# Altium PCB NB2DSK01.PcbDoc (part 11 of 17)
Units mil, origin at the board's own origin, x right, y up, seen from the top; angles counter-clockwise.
Board outline 11815 x 6500.03 mil, 8 copper layers (Top Layer, MidLayer1, MidLayer2, GND, PWR, MidLayer3, MidLayer4, Bottom Layer), stack 74.62 mil thick; 798 components, 1002 nets, 3927 pads, 3182 vias.
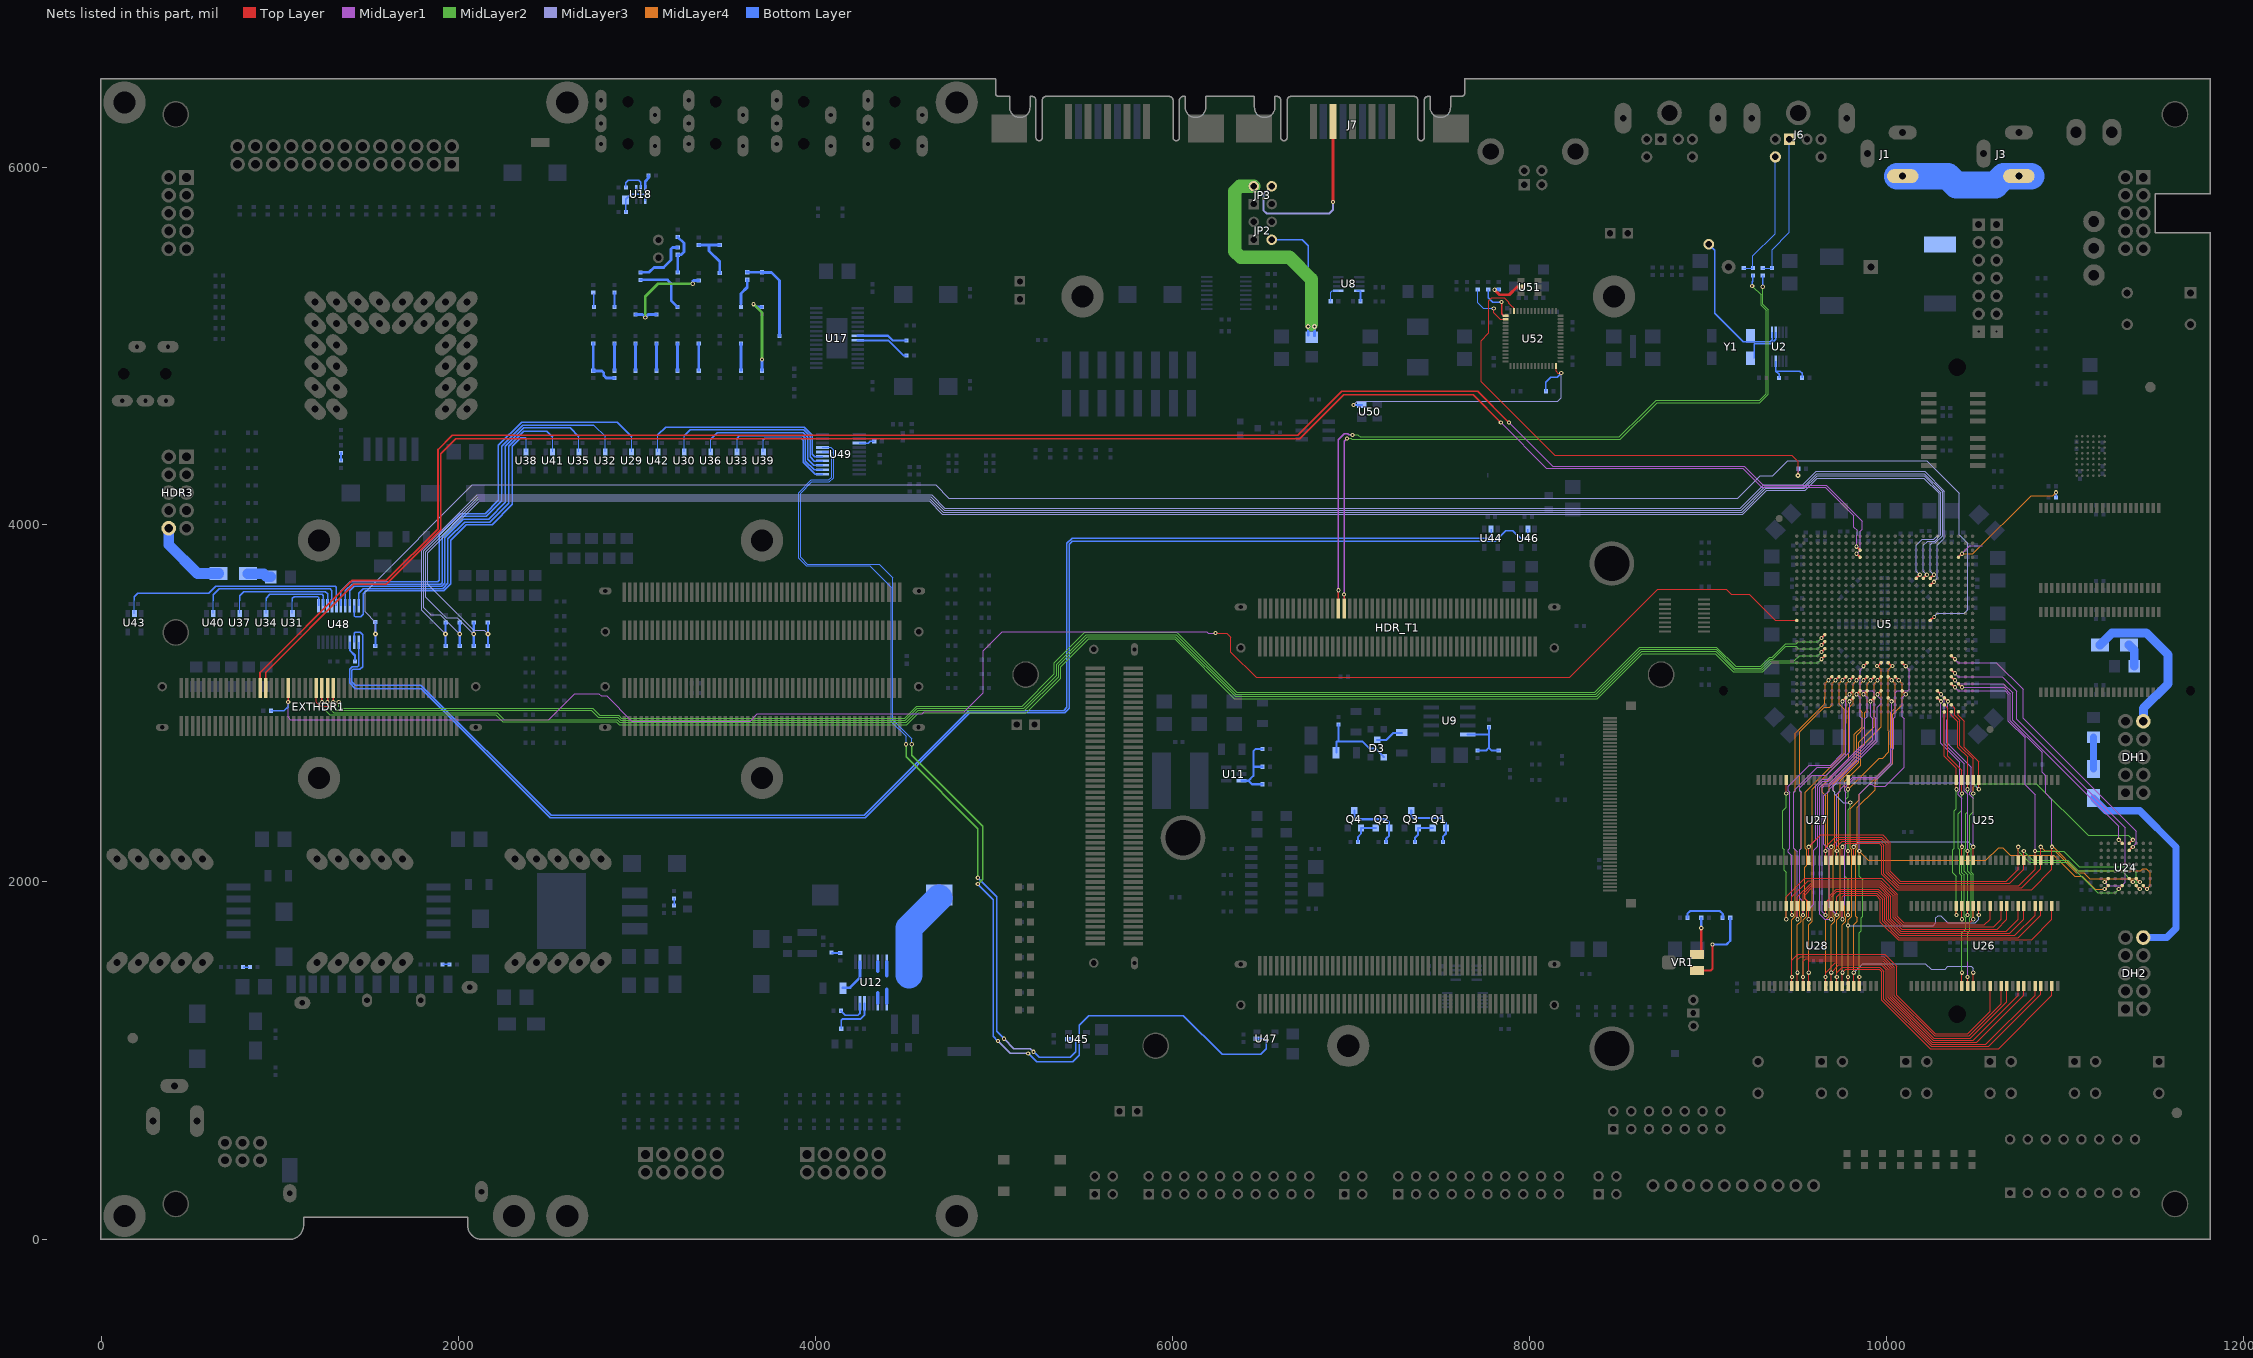
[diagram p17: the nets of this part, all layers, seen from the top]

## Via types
v1: diameter 23.62, hole 11.81, Top Layer to Bottom Layer, tented both sides, 1950 vias
v2: diameter 27.56, hole 11.81, Top Layer to Bottom Layer, tented both sides, 679 vias
v3: diameter 23.62, hole 11.81, Top Layer to Bottom Layer, 194 vias
v4: diameter 31.5, hole 11.81, Top Layer to Bottom Layer, tented both sides, 178 vias
v5: diameter 21.65, hole 11.81, Top Layer to Bottom Layer, tented both sides, 67 vias
v6: diameter 23.62, hole 11.81, Top Layer to Bottom Layer, tented bottom, 53 vias
v7: diameter 26, hole 11.81, Top Layer to Bottom Layer, tented both sides, 21 vias
v8: diameter 26, hole 11.81, Top Layer to Bottom Layer, 13 vias
v9: diameter 28, hole 11.81, Top Layer to Bottom Layer, 8 vias
v10: diameter 25.59, hole 11.81, Top Layer to Bottom Layer, tented both sides, 7 vias
v11: diameter 39.37, hole 11.81, Top Layer to Bottom Layer, tented both sides, 5 vias
v12: diameter 30, hole 11.81, Top Layer to Bottom Layer, 3 vias
v13: diameter 30, hole 11.81, Top Layer to Bottom Layer, tented both sides, 2 vias
v14: diameter 23, hole 11.81, Top Layer to Bottom Layer, tented both sides, 1 vias
v15: diameter 26.56, hole 11.81, Top Layer to Bottom Layer, tented both sides, 1 vias

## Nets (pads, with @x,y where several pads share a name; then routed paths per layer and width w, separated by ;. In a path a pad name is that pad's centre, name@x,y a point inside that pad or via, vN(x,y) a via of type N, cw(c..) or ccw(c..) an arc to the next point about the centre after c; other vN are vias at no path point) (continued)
MEM.BUS_D11: U5.AC10 U24.G4 U25.47 U27.32 | length 3388.4
  Top Layer w5: U27.32@9562.99,2122.05 v1(9562.99,2196.85) 9629.92,2263.78 9976.38,2263.78 10019.69,2220.47 10019.69,2059.06 10074.8,2003.94 10669.29,2003.94 10736.22,2070.87 U25.47@10736.22,2122.05 v1(10736.22,2196.85) ; v1(11299.21,1960.45) U24.G4@11318.9,1980.14
  Top Layer w7.87: v1(9830.71,3051.18) U5.AC10@9850.39,3070.87
  MidLayer1 w5: v1(9562.99,2196.85) 9602.36,2236.22 9602.36,2539.37 9637.8,2574.8 9669.29,2574.8 9862.2,2767.72 9862.2,2870.08 9862.2,2889.76 9862.2,2913.39 9850.39,2925.2 9850.39,3031.5 v1(9830.71,3051.18)
  MidLayer2 w5: v1(10736.22,2196.85) 10736.22,2173.23 10799.21,2110.24 11011.81,2110.24 11181.55,1940.5 11279.26,1940.5 v1(11299.21,1960.45)
MEM.BUS_D12: U5.AA10 U24.F5 U25.48 U27.35 | length 3327.5
  Top Layer w5: U27.35@9657.48,2122.05 v1(9657.48,2173.23) 9657.48,2196.85 9712.6,2251.97 9972.44,2251.97 10007.87,2216.54 10007.87,2055.12 10070.87,1992.13 10688.98,1992.13 10767.72,2070.87 U25.48@10767.72,2122.05 v1(10767.72,2173.23) ; U24.F5@11358.27,2019.51 v1(11377.95,1999.82)
  Top Layer w7.87: v1(9830.71,3129.92) U5.AA10@9850.39,3149.61
  MidLayer2 w5: v1(10767.72,2173.23) 10818.9,2122.05 11014.14,2122.05 11073.38,2062.81 11314.96,2062.81 v1(11377.95,1999.82)
  MidLayer4 w5: v1(9657.48,2173.23) 9657.48,2484.25 9637.8,2503.94 9637.8,2539.37 9754.26,2655.84 9787.4,2688.98 9787.4,2870.08 9787.4,2889.76 9787.4,2976.38 9811.02,3000 9811.02,3110.24 v1(9830.71,3129.92)
MEM.BUS_D13: U5.AB23 U24.G6 U25.50 U27.36 | length 3604.8
  Top Layer w5: U27.36@9688.98,2122.05 v1(9688.98,2196.85) 9732.28,2240.16 9968.5,2240.16 9996.06,2212.6 9996.06,2051.18 10066.93,1980.32 10740.16,1980.32 10830.71,2070.87 U25.50@10830.71,2122.05 v1(10830.71,2173.23) ; U24.G6@11397.64,1980.14 v1(11417.32,1960.45)
  Top Layer w7.87: U5.AB23@10362.2,3110.24 v1(10381.89,3090.55)
  MidLayer1 w5: v1(10381.89,3090.55) 10401.58,3070.87 10663.02,3070.87 10681.1,3052.79 10681.1,2901.03 10775.59,2806.54 10775.59,2543.31 10830.71,2488.19 v1(10830.71,2173.23)
  MidLayer2 w5: v1(10830.71,2173.23) 10991.25,2173.23 11078.04,2086.44 11362.2,2086.44 11397.64,2051 11397.64,1980.14 v1(11417.32,1960.45)
MEM.BUS_D14: U5.AD14 U24.F6 U25.51 U27.37 | length 3331.5
  Top Layer w5: U27.37@9720.47,2122.05 9720.47,2196.85 9751.97,2228.35 9960.63,2228.35 9984.25,2204.72 9984.25,2047.24 10062.99,1968.5 10755.91,1968.5 10862.21,2074.8 U25.51@10862.21,2122.05 v1(10862.21,2196.85) ; U24.F6@11397.64,2019.51 v1(11417.32,1999.82)
  Top Layer w7.87: U5.AD14@10007.87,3031.5 v1(10027.56,3011.81)
  MidLayer1 w5: v1(9720.47,2173.23) 9720.47,2492.13 9740.16,2511.81 9740.16,2519.69 9808.47,2588 9941.3,2588 10021,2667.7 10021,2745.41 10027.56,2751.97 10027.56,2870.08 10027.56,2889.77 v1(10027.56,3011.81)
  MidLayer4 w5: v1(10862.21,2196.85) 10884.56,2174.49 10939.51,2174.49 11061.18,2052.82 11103.61,2052.82 11136.92,2019.51 11397.64,2019.51 v1(11417.32,1999.82)
MEM.BUS_D15: U5.AB24 U24.G7 U25.53 U27.38 | length 3639.8
  Top Layer w5: U27.38@9751.97,2122.05 v1(9751.97,2196.85) 9771.65,2216.54 9956.69,2216.54 9972.44,2200.79 9972.44,2043.31 10059.06,1956.69 10811.02,1956.69 10925.2,2070.87 U25.53@10925.2,2122.05 v1(10925.2,2196.85) ; U24.G7@11437.01,1980.14 v1(11456.69,1960.45)
  Top Layer w7.87: U5.AB24@10401.58,3110.24 v1(10421.26,3090.55)
  MidLayer1 w5: v1(10421.26,3090.55) 10543.31,3090.55 10562.99,3090.55 10657.48,3090.55 10692.91,3055.12 10692.91,2903.36 10870.08,2726.2 10870.08,2614.17 10889.76,2594.49 10889.76,2496.06 10925.2,2460.63 v1(10925.2,2196.85)
  MidLayer4 w5: v1@10931.29,2196.85 11065.33,2062.82 11421.26,2062.82 11433.07,2074.63 11452.76,2074.63 11476.38,2051 11476.38,1980.14 v1(11456.69,1960.45)
MEM.BUS_D16: U5.W16 U26.2 U28.7 | length 3327.3
  Top Layer w5: v1(9751.97,1791.34) U28.7@9751.97,1866.14 9751.97,1917.32 9759.84,1925.2 9940.94,1925.2 9964.57,1901.57 9964.57,1775.59 10062.99,1677.17 10811.02,1677.17 10925.2,1791.34 U26.2@10925.2,1866.14
  Top Layer w7.87: U5.W16@10086.61,3228.35 v1(10106.3,3208.66)
  MidLayer1 w5: v1(9751.97,1791.34) 9751.97,1862.2 9763.78,1874.02 9763.78,2181.1 9771.65,2188.98 9771.65,2503.94 9763.78,2511.81 9763.78,2527.56 9814.22,2578 9945.44,2578 10031,2663.56 10031,2739.66 10039.37,2748.03 10039.37,2870.08 10039.37,2889.76 10039.37,2917.32 10047.24,2925.2 10047.24,3059.06 10059.06,3070.87 10118.11,3070.87 10125.98,3078.74 10125.98,3188.98 v1(10106.3,3208.66)
MEM.BUS_D17: U5.AC13 U26.4 U28.8 | length 2966.9
  Top Layer w5: v1(9720.47,1814.96) U28.8@9720.47,1866.14 9720.47,1917.32 9740.16,1937.01 9943.27,1937.01 9976.38,1903.9 9976.38,1779.53 10066.93,1688.98 10737.18,1688.98 10862.21,1814 U26.4@10862.21,1866.14
  Top Layer w7.87: v1(9948.82,3051.18) U5.AC13@9968.5,3070.87
  MidLayer1 w5: v1(9720.47,1814.96) 9696.85,1838.58 9677.5,1857.93 9677.5,2180.7 9647.8,2210.4 9647.8,2482.2 9676.79,2511.19 9676.79,2519.31 9947.01,2789.53 9947.01,2978.5 9968.5,3000 9968.5,3020.8 9948.82,3040.48 v1(9948.82,3051.18)
MEM.BUS_D18: U5.AD12 U26.5 U28.9 | length 2996.6
  Top Layer w5: v1(9688.98,1791.34) U28.9@9688.98,1866.14 9688.98,1917.32 9720.47,1948.82 9948.82,1948.82 9988.19,1909.45 9988.19,1783.46 10070.87,1700.79 10716.5,1700.79 10830.71,1815 U26.5@10830.71,1866.14
  Top Layer w7.87: v1(9909.45,3011.81) U5.AD12@9929.13,3031.5
  MidLayer1 w5: v1(9688.98,1791.34) 9653.54,1791.34 9625.98,1818.9 9625.98,2531.5 9645.67,2551.18 9677.17,2551.18 9921.26,2795.28 9921.26,2870.08 9921.26,2889.76 9921.26,2913.39 9909.45,2925.2 v1(9909.45,3011.81)
MEM.BUS_D19: U5.W11 U26.7 U28.10 | length 3141.9
  Top Layer w5: U28.10@9653.54,1881.89 9677.17,1905.51 9677.17,1921.26 9716.54,1960.63 9952.76,1960.63 10000,1913.39 10000,1787.4 10074.8,1712.6 10688.98,1712.6 10767.72,1791.34 U26.7@10767.72,1866.14 ; v1(9657.48,1814.96) U28.10@9657.48,1866.14
  Top Layer w7.87: v1(9870.08,3208.66) U5.W11@9889.76,3228.35
  MidLayer1 w5: v1(9657.48,1814.96) 9637.8,1834.65 9637.8,2527.56 9649.61,2539.37 9681.1,2539.37 9937.01,2795.28 9937.01,2870.08 9937.01,2889.76 9937.01,2917.32 9929.13,2925.2 9929.13,3059.06 9917.32,3070.87 9858.27,3070.87 9850.39,3078.74 9850.39,3188.98 v1(9870.08,3208.66)
MEM.BUS_D20: U5.AC11 U26.8 U28.13 | length 3065.8
  Top Layer w5: v1(9562.99,1791.34) U28.13@9562.99,1866.14 ; U28.13@9562.99,1885.83 9543.31,1905.51 9543.31,1929.13 9586.61,1972.44 9956.69,1972.44 10011.81,1917.32 10011.81,1791.34 10078.74,1724.41 10669.29,1724.41 10736.22,1791.34 U26.8@10736.22,1866.14
  Top Layer w7.87: v1(9870.08,3051.18) U5.AC11@9889.76,3070.87
  MidLayer1 w5: v1(9562.99,1791.34) 9562.99,1846.46 9590.55,1874.02 9590.55,2177.17 9614.17,2200.79 9614.17,2535.43 9641.73,2562.99 9673.23,2562.99 9877.95,2767.72 9877.95,2870.08 9877.95,2889.76 9877.95,2913.39 9889.76,2925.2 9889.76,3031.5 v1(9870.08,3051.18)
MEM.BUS_D21: U5.AD9 U26.10 U28.14 | length 2956.5
  Top Layer w5: v1(9531.5,1814.96) U28.14@9531.5,1866.14 9531.5,1933.07 9582.68,1984.25 9960.63,1984.25 10023.62,1921.26 10023.62,1795.28 10082.68,1736.22 10618.11,1736.22 10673.23,1791.34 U26.10@10673.23,1866.14
  Top Layer w7.87: v1(9791.34,3011.81) U5.AD9@9811.02,3031.5
  MidLayer1 w5: v1(9531.5,1814.96) 9531.5,1889.76 9511.81,1909.45 9511.81,2181.1 9519.69,2188.98 9519.69,2503.94 9511.81,2511.81 9511.81,2527.56 9582.68,2598.43 9661.42,2598.43 9791.34,2728.35 9791.34,2870.08 9791.34,2889.77 v1(9791.34,3011.81)
MEM.BUS_D22: U5.AC9 U26.11 U28.15 | length 3039.5
  Top Layer w5: v1(9500,1791.34) U28.15@9500,1866.14 9500,1917.32 9578.74,1996.06 9962.96,1996.06 10035.43,1923.59 10035.43,1799.21 10086.61,1748.03 10598.42,1748.03 10641.73,1791.34 U26.11@10641.73,1866.14
  Top Layer w7.87: v1(9791.34,3051.18) U5.AC9@9811.02,3070.87
  MidLayer1 w5: v1(9500,1791.34) 9500,2169.29 9480.32,2188.98 9480.32,2503.94 9488.19,2511.81 9488.19,2519.69 9610.24,2641.73 9688.98,2641.73 9771.65,2724.41 9771.65,2870.08 9771.65,2889.76 9771.65,3031.5 v1(9791.34,3051.18)
MEM.BUS_D23: U5.AD8 U26.13 U28.16 | length 2947.9
  Top Layer w5: v1(9468.5,1814.96) U28.16@9468.5,1866.14 9468.5,1917.32 9559.06,2007.87 9967.26,2007.87 10047.24,1927.89 10047.24,1803.15 10090.55,1759.84 10547.24,1759.84 10578.74,1791.34 U26.13@10578.74,1866.14
  Top Layer w7.87: v1(9751.97,3011.81) U5.AD8@9771.65,3031.5
  MidLayer1 w5: v1(9468.5,1814.96) 9468.5,2145.67 9448.82,2165.35 9448.82,2181.1 9456.69,2188.98 9456.69,2503.94 9448.82,2511.81 9448.82,2535.43 9566.93,2653.54 9685.04,2653.54 9751.97,2720.47 v1(9751.97,3011.81)
MEM.BUS_D24: U5.AA6 U26.42 U28.29 | length 3522
  Top Layer w5: U28.29@9468.5,1417.32 v1(9468.5,1468.5) 9468.5,1562.5 9500.49,1594.49 9988.19,1594.49 10055.12,1527.56 10055.12,1366.14 10271.65,1149.61 10452.76,1149.61 10578.74,1275.59 U26.42@10578.74,1417.32
  Top Layer w7.87: v1(9673.23,3129.92) U5.AA6@9692.91,3149.61
  MidLayer4 w5: v1(9468.5,1468.5) 9468.5,1787.4 9488.19,1807.09 9488.19,2181.1 9480.32,2188.98 9480.32,2503.94 9488.19,2511.81 9488.19,2833.19 9653.54,2998.54 9653.54,3034.59 9653.54,3110.23 v1(9673.23,3129.92)
MEM.BUS_D25: U5.AA7 U26.44 U28.30 | length 3534.2
  Top Layer w5: U28.30@9500,1417.32 v1(9500,1492.13) 9500,1564 9518.68,1582.68 9984.25,1582.68 10043.31,1523.62 10043.31,1362.2 10267.72,1137.8 10460.63,1137.8 10641.73,1318.9 U26.44@10641.73,1417.32
  Top Layer w7.87: v1(9712.6,3129.92) U5.AA7@9732.28,3149.61
  MidLayer4 w5: v1(9500,1492.13) 9500,1759.84 9519.69,1779.53 9519.69,1799.21 9511.81,1807.09 9511.81,2181.1 9519.69,2188.98 9519.69,2503.94 9511.81,2511.81 9511.81,2842.67 9649.14,2980 9681.68,2980 9692.91,2991.24 9692.91,3110.23 v1(9712.6,3129.92)
MEM.BUS_D26: U5.AA8 U26.45 U28.31 | length 3558.3
  Top Layer w5: U28.31@9531.5,1417.32 v1(9531.5,1468.5) 9531.5,1556.5 9545.87,1570.87 9980.32,1570.87 10031.5,1519.69 10031.5,1358.27 10263.78,1125.98 10468.5,1125.98 10673.23,1330.71 U26.45@10673.23,1417.32
  Top Layer w7.87: v1(9751.97,3129.92) U5.AA8@9771.65,3149.61
  MidLayer4 w5: v1(9531.5,1468.5) 9531.5,1787.4 9551.18,1807.09 9551.18,1893.7 9539.37,1905.51 9539.37,2082.68 9551.18,2094.49 9551.18,2181.1 9543.31,2188.98 9543.31,2503.94 9761.65,2722.28 9761.65,2968.43 9732.28,2997.8 9732.28,3110.23 v1(9751.97,3129.92)
MEM.BUS_D27: U5.AA9 U26.47 U28.32 | length 3508.5
  Top Layer w5: U28.32@9562.99,1417.32 v1(9562.99,1492.13) 9562.99,1557.29 9564.76,1559.06 9976.38,1559.06 10019.69,1515.75 10019.69,1354.33 10259.84,1114.17 10484.25,1114.17 10736.22,1366.14 U26.47@10736.22,1417.32
  Top Layer w7.87: v1(9791.34,3129.92) U5.AA9@9811.02,3149.61
  MidLayer4 w5: v1(9562.99,1492.13) 9562.99,1759.84 9582.68,1779.53 9582.68,2519.69 9771.65,2708.66 9771.65,2870.08 9771.65,2889.76 9771.65,3110.23 v1(9791.34,3129.92)
MEM.BUS_D28: U5.AA11 U26.48 U28.35 | length 3440.8
  Top Layer w5: U28.35@9657.48,1417.32 v1(9657.48,1468.5) 9657.48,1492.13 9712.6,1547.24 9972.44,1547.24 10007.87,1511.81 10007.87,1350.39 10255.91,1102.36 10503.94,1102.36 10767.72,1366.14 U26.48@10767.72,1417.32
  Top Layer w7.87: v1(9870.08,3129.92) U5.AA11@9889.76,3149.61
  MidLayer4 w5: v1(9657.48,1468.5) 9657.48,1787.4 9677.17,1807.09 9677.17,2181.1 9669.29,2188.98 9669.29,2503.94 9677.17,2511.81 9677.17,2547.24 9818.9,2688.98 9818.9,2826.77 9862.2,2870.08 9862.2,2889.76 9862.2,2948.82 9850.39,2960.63 9850.39,3110.24 v1(9870.08,3129.92)
MEM.BUS_D29: U5.AA12 U26.50 U28.36 | length 3448.6
  Top Layer w5: U28.36@9688.98,1417.32 v1(9688.98,1492.13) 9732.28,1535.43 9968.5,1535.43 9996.06,1507.87 9996.06,1346.46 10251.97,1090.55 10555.12,1090.55 10830.71,1366.14 U26.50@10830.71,1417.32
  Top Layer w7.87: v1(9909.45,3129.92) U5.AA12@9929.13,3149.61
  MidLayer4 w5: v1(9688.98,1492.13) 9688.98,1759.84 9708.66,1779.53 9708.66,1799.21 9700.79,1807.09 9700.79,2181.1 9708.66,2188.98 9708.66,2503.94 9700.79,2511.81 9700.79,2551.18 9830.71,2681.1 9830.71,2822.84 9877.95,2870.08 9877.95,2889.76 9877.95,2948.82 9889.76,2960.63 9889.76,3110.24 v1(9909.45,3129.92)
MEM.BUS_D30: U5.AA13 U26.51 U28.37 | length 3464.4
  Top Layer w5: U28.37@9720.47,1417.32 v1(9720.47,1468.5) 9720.47,1492.13 9751.97,1523.62 9960.63,1523.62 9984.25,1500 9984.25,1342.52 10248.03,1078.74 10570.87,1078.74 10862.21,1370.08 U26.51@10862.21,1417.32
  Top Layer w7.87: v1(9948.82,3129.92) U5.AA13@9968.5,3149.61
  MidLayer4 w5: v1(9720.47,1468.5) 9720.47,1787.4 9740.16,1807.09 9740.16,2181.1 9732.28,2188.98 9732.28,2503.94 9740.16,2511.81 9740.16,2566.93 9842.52,2669.29 9842.52,2783.47 9929.13,2870.08 9929.13,2889.76 9929.13,3110.24 v1(9948.82,3129.92)
MEM.BUS_D31: U5.W13 U26.53 U28.38 | length 3563.1
  Top Layer w5: U28.38@9751.97,1417.32 v1(9751.97,1492.13) 9771.65,1511.81 9956.69,1511.81 9972.44,1496.06 9972.44,1338.58 10244.09,1066.93 10625.99,1066.93 10925.2,1366.14 U26.53@10925.2,1417.32
  Top Layer w7.87: v5@9948.82,3208.66 U5.W13@9968.5,3228.35
  MidLayer4 w5: v1(9751.97,1492.13) 9751.97,1759.84 9771.65,1779.53 9771.65,1799.21 9763.78,1807.09 9763.78,2181.1 9771.65,2188.98 9771.65,2503.94 9763.78,2511.81 9763.78,2562.99 9854.33,2653.54 9854.33,2755.91 9968.5,2870.08 9968.5,2889.76 9968.5,3188.98 v5@9948.82,3208.66
  other v5: 9944.88,3208.66
MEM.BUS_FLASH_NBUSY: U5.AA23 U24.A4 | length 1477.1
  Top Layer w5: v1(11299.21,2236.04) U24.A4@11318.9,2216.36
  Top Layer w7.87: U5.AA23@10362.2,3149.61 v1(10381.89,3129.92)
  MidLayer1 w5: v1(10381.89,3129.92) 10401.58,3110.24 10543.31,3110.24 10562.99,3110.24 10653.54,3110.24 10704.72,3059.06 10704.72,2905.69 11299.21,2311.2 v1(11299.21,2236.04)
MEM.BUS_FLASH_NCS: U5.Y23 U24.F2 | length 1893.3
  Top Layer w5: v1(11220.47,1999.82) U24.F2@11240.16,2019.51
  Top Layer w7.87: U5.Y23@10362.2,3188.98 v1(10381.89,3169.29)
  MidLayer1 w5: v1(10381.89,3169.29) 10401.58,3149.61 10543.31,3149.61 10562.99,3149.61 10645.67,3149.61 10728.35,3066.93 10728.35,2910.36 11334.65,2304.06 11334.65,1999.82 11314.96,1980.14 11240.16,1980.14 v1(11220.47,1999.82)
MEM.BUS_FLASH_NRESET: U5.V23 U24.B5 | length 1660.5
  Top Layer w5: U24.B5@11358.27,2176.99 v1(11377.95,2196.67)
  Top Layer w7.87: U5.V23@10362.2,3267.72 v1(10381.89,3248.03)
  MidLayer1 w5: v1(10381.89,3248.03) 10401.58,3228.35 10543.31,3228.35 10562.99,3228.35 10614.17,3228.35 10763.78,3078.74 10763.78,2917.35 11397.64,2283.49 11397.64,2216.36 v1(11377.95,2196.67)
MEM.BUS_NBE0: U5.AF24 U25.15 U27.39 | length 1798.6
  Top Layer w5: U27.39@9783.46,2122.05 v1(9783.46,2173.23) ; U5.AF24@10401.58,2952.76 10401.58,2933.07 10433.07,2901.58 10433.07,2889.77 10433.07,2870.08 10433.07,2755.91 10515.75,2673.23 U25.15@10515.75,2570.87 v1(10515.75,2519.69)
  MidLayer2 w5: v1(9783.46,2173.23) 9783.46,2405.51 9795.28,2417.32 v1(9795.28,2444.88)
  MidLayer3 w5: v1(9795.28,2444.88) 9755.91,2444.88 9708.66,2492.13 9708.66,2503.94 9700.79,2511.81 9700.79,2535.43 9720.47,2555.12 10480.32,2555.12 v1(10515.75,2519.69)
MEM.BUS_NBE1: U5.AD22 U25.39 U27.40 | length 1755.4
  Top Layer w5: U27.40@9814.96,2122.05 v1(9814.96,2196.85) ; U25.39@10484.25,2122.05 v1(10484.25,2196.85)
  Top Layer w7.87: U5.AD22@10322.83,3031.5 v1(10342.52,3011.81)
  MidLayer1 w5: v1(10342.52,3011.81) 10342.52,2913.24 10335.68,2906.4 10335.68,2778.45 10472.44,2641.69 10472.44,2511.81 10464.57,2503.94 10464.57,2488.19 10484.25,2468.5 v1(10484.25,2196.85)
  MidLayer3 w5: v1(9814.96,2196.85) 9842.52,2224.41 10456.69,2224.41 v1(10484.25,2196.85)
MEM.BUS_NBE2: U5.AA14 U26.15 U28.39 | length 2734.9
  Top Layer w5: U28.39@9783.46,1417.32 v1(9783.46,1468.5) ; v1(10515.75,1814.96) U26.15@10515.75,1866.14
  Top Layer w7.87: U5.AA14@10007.87,3149.61 v1(10027.56,3129.92)
  MidLayer4 w5: v1(9783.46,1468.5) v1(9783.46,1755.91) 9783.46,1787.4 9803.15,1807.09 9803.15,2181.1 9795.28,2188.98 9795.28,2409.45 9846.46,2460.63 9846.46,2492.13 10023.68,2669.35 10023.68,2950.44 10047.24,2974 10047.24,3110.24 v1(10027.56,3129.92)
  MidLayer3 w5: v1(9783.46,1755.91) 10259.84,1755.91 10275.59,1771.65 10275.59,1799.21 10287.4,1811.02 10303.15,1811.02 10342.52,1771.65 10496.06,1771.65 10515.75,1791.34 v1(10515.75,1814.96)
MEM.BUS_NBE3: U5.AA15 U26.39 U28.40 | length 2681
  Top Layer w5: U28.40@9814.96,1417.32 v1(9814.96,1492.13) ; U26.39@10484.25,1417.32 v1(10484.25,1492.13)
  Top Layer w7.87: U5.AA15@10047.24,3149.61 v1(10066.93,3129.92)
  MidLayer4 w5: v1(9814.96,1492.13) 9814.96,1759.84 9834.65,1779.53 9834.65,1799.21 9826.77,1807.09 9826.77,2181.1 9834.65,2188.98 9834.65,2417.32 9934.68,2517.35 9934.68,2566.2 10034.9,2666.43 10034.9,2940.29 10086.61,2992 10086.61,3110.24 v1(10066.93,3129.92)
  MidLayer3 w5: v1(9814.96,1492.13) 9866.14,1543.31 10216.53,1543.31 10248.03,1511.81 10326.77,1511.81 10342.52,1527.56 10472.44,1527.56 10484.25,1515.75 v1(10484.25,1492.13)
MEM.BUS_NOE: U5.AC16 U24.G2 U27.41 U28.41 | length 3466.3
  Top Layer w5: U28.41@9846.46,1417.32 v1(9846.46,1468.5) ; U27.41@9846.46,2122.05 v1(9846.46,2173.23) ; v1(11220.47,1960.45) U24.G2@11240.16,1980.14
  Top Layer w7.87: U5.AC16@10086.61,3070.87 v1(10106.3,3051.18)
  MidLayer1 w5: v1(9846.46,2173.23) 9846.46,2492.13 9902.76,2548.44 9916,2548.44 9928.98,2535.45 9992.62,2535.45 10098.43,2641.26 10098.43,2913.39 10086.62,2925.2 10086.62,3031.5 v1(10106.3,3051.18)
  MidLayer2 w5: v1(9846.46,1468.5) 9846.46,1716.54 9858.27,1728.35 9858.27,1799.21 9866.14,1807.09 9866.14,2011.81 9846.46,2031.5 v1(9846.46,2173.23)
  MidLayer4 w5: v1(9846.46,2173.23) 9897.64,2122.05 10555.12,2122.05 10625.98,2192.91 10649.61,2192.91 10692.07,2150.45 10935.26,2150.45 11052.9,2032.82 11095.32,2032.82 11167.69,1960.45 v1(11220.47,1960.45)
MEM.BUS_NWE: U5.AE23 U24.A5 U25.16 U26.16 U27.17 U28.17 | length 4633.7
  Top Layer w5: v1(9437.01,1791.34) U28.17@9437.01,1866.14 9437.01,1917.32 9539.37,2019.69 9971.45,2019.69 10059.06,1932.08 10059.06,1807.09 10094.49,1771.65 10464.57,1771.65 v1(10484.25,1791.34) U26.16@10484.25,1866.14 ; v1(9437.01,2496.06) U27.17@9437.01,2570.87 ; U5.AE23@10362.2,2992.13 10381.89,2972.44 10381.89,2933.07 10409.45,2905.51 10409.45,2889.76 10409.45,2870.08 10409.45,2763.78 10484.25,2688.98 U25.16@10484.25,2570.87 v1(10484.25,2496.06) ; U24.A5@11358.27,2216.36 v1(11377.95,2236.04)
  MidLayer2 w5: v1(9437.01,1791.34) 9437.01,2011.81 9437.01,2055.12 9425.2,2066.93 9425.2,2181.1 9417.32,2188.98 9417.32,2397.64 9437.01,2417.32 v1(9437.01,2496.06) ; v1(10484.25,1791.34) 10484.25,2043.31 10472.44,2055.12 10472.44,2181.1 10464.57,2188.98 10464.57,2374.02 10484.25,2393.7 v1(10484.25,2496.06) 10484.25,2531.5 10503.94,2551.18 10837.12,2551.18 11127.1,2261.2 11352.8,2261.2 v1(11377.95,2236.04)
MEM.BUS_SDRAM_CKE: U5.AD21 U25.37 U26.37 | length 1768.9
  Top Layer w5: U26.37@10421.26,1417.32 v1(10421.26,1492.13) ; U25.37@10421.26,2122.05 v1(10421.26,2196.85)
  Top Layer w7.87: U5.AD21@10283.46,3031.5 v1(10303.15,3011.81)
  MidLayer1 w5: v1(10303.15,3011.81) 10303.15,2889.76 10303.15,2870.08 10303.15,2776.99 10409.45,2670.68 10409.45,2511.81 10401.58,2503.94 10401.58,2488.19 10421.26,2468.5 v1(10421.26,2196.85)
  MidLayer2 w5: v1(10421.26,1492.13) 10421.26,1716.54 10440.95,1736.22 10440.95,1799.21 10433.07,1807.09 10433.07,2039.37 10421.26,2051.18 10421.26,2059.06 v1(10421.26,2196.85)
MEM.BUS_SDRAM_CLK: NT3.2 U5.AC21 U25.38 U26.38 | length 1875
  Top Layer w5: U26.38@10452.76,1417.32 v1(10452.76,1468.5) ; U25.38@10452.76,2122.05 v1(10452.76,2173.23)
  Top Layer w7.87: U5.AC21@10283.46,3070.87 v1(10303.15,3051.18)
  MidLayer1 w5: v1(10303.15,3051.18) 10322.83,3031.5 10322.83,2889.76 10322.83,2870.08 10322.83,2773.3 10433.07,2663.06 10433.07,2511.81 10452.76,2492.13 v1(10452.76,2173.23) ; v1(10452.76,1468.5) NT3.2@10452.76,1552.36
  MidLayer2 w5: v1(10452.76,1468.5) 10452.76,1716.54 10464.57,1728.35 10464.57,1799.21 10472.44,1807.09 10472.44,2039.37 10452.76,2059.06 v1(10452.76,2173.23)
MEM.BUS_SDRAM_NCAS: U5.AF23 U25.17 U26.17 | length 1242.8
  Top Layer w5: U5.AF23@10362.2,2952.76 10362.21,2933.07 10397.64,2897.64 10397.64,2889.76 10397.64,2870.08 10397.64,2755.91 10452.76,2700.79 U25.17@10452.76,2570.87 v1(10452.76,2519.69) ; v1(10452.76,1814.96) U26.17@10452.76,1866.14
  MidLayer2 w5: v1(10452.76,1814.96) 10452.76,2039.37 10433.07,2059.06 10433.07,2181.1 10440.95,2188.98 10440.95,2381.89 10452.76,2393.7 v1(10452.76,2519.69)
MEM.BUS_SDRAM_NCS: U5.AF22 U25.19 U26.19 | length 1233
  Top Layer w5: U5.AF22@10322.83,2952.76 10322.84,2704.3 10389.76,2637.37 U25.19@10389.76,2570.87 v1(10389.76,2519.69) ; v1(10389.76,1814.96) U26.19@10389.76,1866.14
  MidLayer2 w5: v1(10389.76,1814.96) 10389.76,2031.49 10370.08,2051.18 10370.08,2181.1 10377.95,2188.98 10377.95,2397.64 10389.76,2409.45 v1(10389.76,2519.69)
MEM.BUS_SDRAM_NRAS: U5.AE22 U25.18 U26.18 | length 1332.7
  Top Layer w5: U5.AE22@10322.83,2992.13 10342.52,2972.44 10342.52,2705.61 10421.26,2626.87 U25.18@10421.26,2570.87 v1(10421.26,2496.06) ; v1(10421.26,1791.34) U26.18@10421.26,1866.14
  MidLayer2 w5: v1(10421.26,1791.34) 10421.26,2035.43 10409.45,2047.24 10409.45,2181.1 10401.58,2188.98 10401.58,2381.89 10421.26,2401.58 v1(10421.26,2496.06)
MEM.BUS_SRAM_NCS: U5.W14 U27.6 U28.6 | length 1656.1
  Top Layer w5: v1(9783.46,1814.96) U28.6@9783.46,1866.14 ; v1(9783.46,2519.69) U27.6@9783.46,2570.87
  Top Layer w7.87: U5.W14@10007.87,3228.35 v5@10027.56,3208.66
  MidLayer2 w5: v1(9783.46,1814.96) 9783.46,2011.81 9763.78,2031.5 9763.78,2181.1 9771.65,2188.98 9771.65,2464.57 9783.46,2476.38 v1(9783.46,2519.69)
  MidLayer4 w5: v1(9783.46,2519.69) 9929.13,2665.36 9956.69,2692.91 9976.38,2692.91 10011.81,2728.35 10011.81,2748.03 10011.81,2842.52 10007.87,2846.46 10007.87,2870.08 10007.87,2889.76 10007.87,3188.98 v5@10027.56,3208.66
  other v5: 10031.5,3208.66
MOUSE#.CLOCK: J6.5 R88.2 R91.2 | length 727
  Bottom Layer w5: R88.2@9198.54,5437.76 R91.2@9250.16,5437.76 9250.16,5505.87 9375.98,5631.7 J6.5@9375.98,6061.02
MOUSE#.DATA: J6.1 R89.2 R90.2 | length 813.7
  Bottom Layer w5: R90.2@9305.71,5437.76 R89.2@9357.32,5437.76 9357.32,5540.2 9454.72,5637.6 J6.1@9454.72,6159.45
MOUSE.CLOCK: HDR_T1.30 R91.1 | length 4267
  Top Layer w5: HDR_T1.30@6929.13,3531.5 v1@6929.13,3637.8
  Top Layer w7.87: HDR_T1.30@6929.13,3531.5 v1(6929.13,3633.86)
  MidLayer1 w7.87: v1(6929.13,3633.86) 6929.13,4476.23 6962.23,4509.33 6982.47,4509.33 6987.86,4503.94 v1(7007.87,4503.94)
  MidLayer2 w5: v1(7007.87,4503.94) 7041.17,4503.94 ; 7041.17,4503.15 7051.87,4492.45 8502.68,4492.45 8633.86,4623.63 8708.23,4698 9287.86,4698 9325,4735.14 9325,5201.36 9295.71,5230.65 9295.71,5288.35 v1(9246.22,5337.83)
  Bottom Layer w7.87: v1(9246.22,5337.83) 9246.22,5360.81 9250.16,5364.74 R91.1@9250.16,5395.39 R91.1@9250.16,5400.04
MOUSE.DATA: HDR_T1.32 R90.1 | length 4100.6
  Top Layer w7.87: HDR_T1.32@6960.63,3531.5 v1(6960.63,3610.24)
  MidLayer1 w7.87: v1(6960.63,3610.24) 6960.63,4468.5 v1(6976.38,4484.25)
  MidLayer2 w5: v1(6976.38,4484.25) 7000,4484.25 7004.8,4479.45 8508.68,4479.45 8714.23,4685 9289,4685 9335,4731 9335,5205.5 9305.71,5234.79 v1(9305.71,5333.9)
  Bottom Layer w7.87: v1(9305.71,5333.9) R90.1@9305.71,5395.39
NetC127_1: C127.1 U8.5 | length 95.5
  Bottom Layer w5: C127.1@6886.49,5252.06 6886.49,5304.19 6893.4,5311.1 U8.5@6927,5311.1
NetC130_1: C130.1 D3.1 R56.1 | length 459.6
  Bottom Layer w11.81: C130.1@6917.32,2724.41 6917.32,2787.4 6929.13,2787.4 ; R56.1@6929.13,2882.36 6929.13,2787.4 ; D3.1@7183.07,2700.79 7135.83,2748.03 7102.36,2748.03 7062.99,2787.4 6929.13,2787.4
NetC131_2: C131.2 D3.3 | length 154.1
  Bottom Layer w11.81: D3.3@7145.67,2795.28 7196.85,2795.28 7236.22,2834.65 C131.2@7283.46,2834.65
NetC145_2: C145.2 U12.6 | length 255.1
  Bottom Layer w10: C145.2@4145.01,1178.45 4145.01,1224.78 4153.68,1233.45 4253.68,1233.45 4274.18,1253.95 U12.6@4274.18,1321.45
NetC151_1: C151.1 U12.10 | length 208
  Bottom Layer w15: C151.1@4153.68,1408.45 4155.77,1408.45 4177.8,1408.45 4193.68,1408.45 4249.18,1463.95 U12.10@4249.18,1553.45
NetC171_1: C171.1 R109.1 | length 150.1
  Bottom Layer w15.75: C171.1@2874.02,4866.14 R109.1@2874.02,5016.22
NetC171_2: C171.2 C172.1 R108.2 | length 295.5
  Bottom Layer w15.75: R108.2@2755.91,5016.22 C172.1@2755.91,4863.19 2755.91,4862.21 2803.15,4862.21 2814.96,4850.39 2814.96,4836.61 2828.74,4822.84 C171.2@2873.03,4822.84
NetC173_1: C173.1 R112.1 | length 150.1
  Bottom Layer w15.75: C173.1@2992.13,4866.14 R112.1@2992.13,5016.22
NetC175_1: C175.1 R113.1 | length 150.1
  Bottom Layer w15.75: C175.1@3346.46,4866.14 R113.1@3346.46,5016.22
NetC176_1: C176.1 R114.1 | length 150.1
  Bottom Layer w15.75: C176.1@3582.68,4866.14 R114.1@3582.68,5016.22
NetC178_1: C178.1 R115.1 | length 75.9
  Bottom Layer w7.87: C178.1@2755.91,5294.29 2759.84,5290.36 R115.1@2759.84,5220
NetC179_1: C179.1 R118.1 | length 300.9
  Bottom Layer w15.75: R118.1@3021.08,5414.63 3068.33,5414.63 3095.9,5442.2 3150.1,5442.2 3191.38,5483.48 3191.38,5544.18 3201.32,5554.12 C179.1@3228.68,5554.12
NetC179_2: C179.2 C181.1 R117.2 | length 238.5
  Bottom Layer w15: R117.2@3228.68,5414.63 C179.2@3228.68,5512.78 3248.01,5512.78 3263.68,5528.45 3263.68,5577.78 C181.1@3228.68,5612.78
NetC182_1: C182.1 R121.1 | length 82.2
  Bottom Layer w11.81: R121.1@2874.02,5220 C182.1@2874.02,5302.17
NetC183_1: C183.1 U17.22 | length 310
  Bottom Layer w11.81: U17.22@4236.22,5033.47 4408.43,5033.47 4493.82,4948.08 C183.1@4510.82,4948.08
NetC184_1: C184.1 R124.1 | length 150.1
  Bottom Layer w15.75: C184.1@3110.24,4866.14 R124.1@3110.24,5016.22
NetC185_1: C185.1 R125.1 | length 153
  Bottom Layer w15.75: C185.1@3228.35,4863.19 R125.1@3228.35,5016.22
NetC186_1: C186.1 R126.1 | length 443.6
  MidLayer2 w15.75: v1(3653.54,5236.22) 3700.79,5188.98 v1(3700.79,4926.77)
  Bottom Layer w15.75: v1(3653.54,5236.22) 3669.76,5220 R126.1@3700.79,5220 ; C186.1@3700.79,4866.14 v1(3700.79,4926.77)
NetC187_2: C187.2 R127.2 R132.1 | length 594.3
  MidLayer2 w15.75: v1(3047.24,5161.42) 3047.24,5279.53 3118.11,5350.39 v1(3312.99,5350.39)
  Bottom Layer w15.75: R132.1@2992.13,5177.64 3031.02,5177.64 v1(3047.24,5161.42) 3063.46,5177.64 R127.2@3110.24,5177.64 ; v1(3312.99,5350.39) 3312.99,5364.55 3317.54,5369.1 C187.2@3346.46,5369.1
NetC188_1: C188.1 R129.1 | length 151.5
  Bottom Layer w15.75: 3582.68,5236.22 3582.68,5295.67 3618.11,5331.1 C188.1@3618.11,5373.03
NetC188_2: C188.2 C189.1 R128.2 | length 513.7
  Bottom Layer w15.75: C188.2@3615.35,5416.54 3617.52,5414.37 C188.2@3618.11,5414.37 C189.1@3700.79,5414.37 3702.17,5412.99 3754.72,5412.99 3799.21,5368.5 R128.2@3799.21,5058.58
NetC190_1: C190.1 R130.2 R131.2 | length 299.9
  Bottom Layer w15.75: R130.2@3346.46,5567.4 3404.55,5567.4 ; C190.1@3464.57,5410.43 3464.57,5474.63 3404.55,5534.64 3404.55,5567.4 ; R131.2@3464.57,5567.4 3404.55,5567.4
NetC197_2: C197.2 R135.1 U18.1 U18.4 | length 260.1
  Bottom Layer w7.87: R135.1@2938.5,5751.97 2938.5,5818.9 2938.5,5824.33 2964.57,5850.39 2996.06,5850.39 ; U18.4@2996.06,5887.8 2996.06,5850.39 ; U18.1@3047.24,5814.96 3047.24,5842.52 3039.37,5850.39 2996.06,5850.39
NetC198_2: C198.2 U18.6 | length 76.6
  Bottom Layer w15.75: U18.6@3047.24,5887.8 3047.24,5923.24 3065.94,5941.94 C198.2@3065.94,5956.68
NetC256_1: C256.1 U48.13 | length 110
  Bottom Layer w12: U48.13@1392.5,3342.24 1392.5,3297.5 1421.18,3268.82 C256.1@1421.18,3244.09
NetC257_1: C257.1 U49.13 | length 89.5
  Bottom Layer w7.87: U49.13@4244.37,4458.46 4297.05,4458.46 4307.09,4468.5 C257.1@4329.72,4468.5
NetD9_1: D9.1 F3.1 | length 129.9
  Bottom Layer w50: D9.1@11357.26,3326.76 11385.83,3298.2 F3.1@11385.83,3208.66
NetD9_2: D9.2 DH1.10 | length 890.6
  Bottom Layer w50: D9.2@11193.88,3326.76 11262.11,3395 11453,3395 11575.58,3272.42 11575.58,3111.01 11437.01,2972.44 DH1.10@11437.01,2900
NetD10_1: D10.1 F4.1 | length 178.1
  Bottom Layer w40: D10.1@11157.46,2632.87 F4.1@11157.46,2811.02
NetD10_2: D10.2 DH2.10 | length 1235.4
  Bottom Layer w40: D10.2@11157.46,2469.48 11227.94,2399 11417,2399 11620,2196 11620,1741 11567.98,1688.98 DH2.10@11437.01,1688.98
NetD11_1: D11.1 F5.1 | length 136.8
  Bottom Layer w59.06: D11.1@821.16,3727.35 909.66,3727.35 928.72,3708.28 F5.1@950.04,3708.28
NetD11_2: D11.2 HDR3.10 | length 438.9
  Bottom Layer w60: HDR3.10@377.95,3981.1 377.95,3889.05 539.66,3727.35 D11.2@657.78,3727.35
NetF1_1: F1.1 J1.1 J3.1 | length 789.4
  Bottom Layer w150: J1.1@10059.24,5952.76 J1.1@10089.37,5952.76 10341.24,5952.76 10390,5904 10607,5904 10655.76,5952.76 J3.1@10739.76,5952.76 J3.1@10808.24,5952.76
NetF2_2: F2.2 JP3.2 | length 1298.7
  MidLayer2 w74.8: JP3.2@6455.12,5896.85 6376.85,5896.85 6349,5869 6349,5531 6382,5498 6655,5498 6778,5375 6778,5124
  Bottom Layer w15.75: F2.2@6759.83,5062.98 v2(6759.83,5110.23) ; F2.2@6795.26,5059.05 v2(6795.26,5110.23)
NetJ7_4: J7.4 JP3.4 | length 1054.9
  Top Layer w15.75: J7.4@6898.74,6259.84 v1(6898.84,5808.9)
  MidLayer3 w11.81: JP3.4@6555.12,5896.85 6509,5850.73 6509,5762 6527,5744 6878,5744 6898.84,5764.84 v1(6898.84,5808.9)
NetJP2_3: JP2.3 R54.1 | length 536.1
  Bottom Layer w7.87: JP2.3@6555.12,5596.85 6727.16,5596.85 6761.21,5562.8 R54.1@6761.21,5251.05 R54.1@6764.16,5253.99
NetL2_1: L2.1 U12.1 U12.3 U12.14 U12.16 | length 770.9
  Bottom Layer w18: 4349.18,1497.95 U12.14@4349.18,1553.45
  Bottom Layer w20: U12.3@4349.18,1321.45 4349.18,1378.95 ; U12.1@4399.18,1321.45 4399.18,1397.95 ; 4399.18,1473.95 U12.16@4399.18,1553.45
  Bottom Layer w150: 4523.68,1478.45 4523.68,1741.58 L2.1@4692.5,1910.4
NetQ1_1: Q1.1 Q3.3 R48.2 | length 353.9
  Bottom Layer w11.81: Q3.3@7336.93,2400.86 7336.94,2370.04 7349.42,2357.55 7501.9,2357.55 7531.82,2327.63 Q1.1@7531.82,2302.43 7531.82,2271.84 7515.6,2255.62 R48.2@7515.6,2223.69
NetQ1_2: Q1.2 Q3.1 R50.2 | length 168.1
  Bottom Layer w11.81: R50.2@7358.12,2223.69 7358.12,2248.25 7374.34,2264.47 Q3.1@7374.34,2302.43 Q1.2@7457.01,2302.43
NetQ2_1: Q2.1 Q4.3 R49.2 | length 360.9
  Bottom Layer w11.81: Q4.3@7018.04,2400.86 7018.04,2363.88 7030.28,2351.65 7194.57,2351.65 7212.92,2333.3 Q2.1@7212.92,2302.43 7212.92,2259.55 7196.7,2243.33 R49.2@7196.7,2223.69
NetQ2_2: Q2.2 Q4.1 R51.2 | length 168.1
  Bottom Layer w9.84: R51.2@7039.22,2223.69 7039.22,2253.61 7055.44,2269.83 Q4.1@7055.44,2302.43
  Bottom Layer w11.81: Q4.1@7055.44,2302.43 Q2.2@7138.12,2302.43
NetR1_1: R1.1 R2.2 U2.9 | length 278.9
  Bottom Layer w7.87: U2.9@9377.97,4916.76 9377.97,4861.03 ; R1.1@9396.76,4823 9396.76,4842.24 9377.97,4861.03 ; R2.2@9525.64,4823.89 9525.64,4848.36 9512.97,4861.03 9377.97,4861.03
NetR16_1: R16.1 U5.D24 | length 877.2
  Top Layer w7.87: U5.D24@10401.58,3818.9 v1(10421.26,3838.58)
  MidLayer1 w5: v1(10421.26,3838.58) 10465,3882.32 10534.68,3882.32
  MidLayer4 w5: v1(10421.26,3838.58) 10482.58,3838.58 10808,4164 10929.96,4164 v1(10948.35,4182.38)
  Bottom Layer w5: R16.1@10948.35,4153.35 v1(10948.35,4182.38) R16.1@10948.35,4163.07
NetR40_1: R40.1 VR1.3 | length 480.1
  Top Layer w11.81: VR1.3@8937.01,1488.19 VR1.3@8952.76,1488.19 ; VR1.3@8937.01,1504.19 9015.19,1504.19 9023.62,1512.62 v1(9023.62,1649.61)
  Bottom Layer w11.81: v1(9023.62,1649.61) 9102.61,1649.61 9123.53,1670.53 R40.1@9123.53,1799.21
NetR40_2: R40.2 R41.1 | length 255.9
  Bottom Layer w11.81: R41.1@8883.37,1799.21 8883.37,1822.37 8898,1837 9066,1837 9081.16,1821.84 R40.2@9081.16,1799.21
NetR42_2: R42.2 VR1.1 | length 230.4
  Top Layer w11.81: VR1.1@8937.01,1578.74 8961,1602.73 v2(8961,1742)
  Bottom Layer w11.81: v2(8961,1742) 8961.08,1764.08 R42.2@8961.08,1799.21
NetR53_2: R53.2 U8.4 | length 76.5
  Bottom Layer w9.84: U8.4@7033.1,5311.1 U8.4@7045.11,5311.1 7048.5,5311.1 7053.15,5306.45 R53.2@7053.15,5251.96
NetR57_1: R57.1 R58.2 R59.2 U9.4 | length 366.5
  Bottom Layer w11.81: U9.4@7653.54,2826.77 7766.32,2826.77 7771.65,2821.43 ; R58.2@7708.54,2735.75 7755.4,2735.75 7771.65,2752 ; R57.1@7771.65,2866.61 7771.65,2821.43 ; R59.2@7826.65,2735.75 7787.9,2735.75 7771.65,2752 ; 7771.65,2752 7771.65,2821.43
NetR61_2: R61.2 R62.1 | length 39.5
  Bottom Layer w7.87: R61.2@3208.68,1869 R62.1@3208.66,1908.45
NetR63_1: R63.1 R64.2 R65.2 U11.3 | length 411.9
  Bottom Layer w11.81: U11.3@6385.83,2566.93 6425.2,2566.93 ; R64.2@6504.41,2547.24 6444.88,2547.24 6425.2,2566.93 ; R65.2@6504.41,2645.67 6452.8,2645.67 6452.76,2645.71 ; R63.1@6504.41,2744.1 6464.24,2744.1 6452.76,2732.61 6452.76,2645.71 ; 6425.2,2566.93 6452.76,2594.49 6452.76,2645.71
NetR68_1: R68.1 R70.2 | length 45.4
  Bottom Layer w11.81: R68.1@4093.32,1602.63 R70.2@4138.68,1602.63
NetR69_2: R69.2 U12.7 | length 178.5
  Bottom Layer w10: R69.2@4142.86,1278.45 4167.86,1253.45 4238.68,1253.45 4249.18,1263.95 U12.7@4249.18,1321.45
NetR73_2: R73.2 R74.1 | length 39.5
  Bottom Layer w8: R74.1@1912.01,1538.45 R73.2@1951.54,1538.45
NetR76_1: R76.1 R77.1 | length 32.6
  Bottom Layer w8: R77.1@794.86,1523.45 R76.1@827.5,1523.45
NetR79_1: R79.1 R80.2 | length 42.6
  Bottom Layer w10: R79.1@1343.68,4361.03 R80.2@1343.68,4403.67
NetR110_2: R110.2 U17.21 | length 285
  Bottom Layer w11.81: U17.21@4236.22,5059.06 4406.62,5059.06 4432.95,5032.72 R110.2@4510.31,5032.72
NetR118_2: R118.2 R119.1 | length 326.4
  Bottom Layer w15: R118.2@3021.08,5372.27 3171.73,5372.27 3192,5352 3192,5256.35 R119.1@3228.35,5220
NetR136_1: R136.1 U18.5 | length 149.7
  Bottom Layer w7.87: R136.1@2938.5,5889.76 2938.5,5914.88 2952.76,5929.13 3011.81,5929.13 3021.65,5919.29 U18.5@3021.65,5887.8
NetR313_2: R313.2 U51.5 | length 201.2
  Top Layer w15.75: v1(7804,5317) 7832,5289 7886,5289 7928.69,5331.69 U51.5@7952.76,5331.69
  Bottom Layer w15.75: v1(7804,5317) 7804.39,5317.39 R313.2@7827.02,5317.39
NetR314_1: R314.1 U50.2 U52.42 | length 1584.2
  Top Layer w5: U52.42@8147.64,4885.24 8147.64,4860.24 8157.48,4850.39 v1(8177.17,4850.39)
  MidLayer3 w5: v1(7013,4670.93) 7034.07,4692 8157,4692 8177.17,4712.17 v1(8177.17,4850.39)
  Bottom Layer w7.87: R314.1@8091.02,4748.03 8091.02,4799.82 8117.98,4826.77 8153.54,4826.77 v1(8177.17,4850.39)
  Bottom Layer w11.81: v1(7013,4670.93) U50.2@7060.24,4670.93
NetR315_2: R315.2 U52.13 | length 2745.9
  Top Layer w5: U52.13@7911.42,5193.9 U52.13@7911.41,5197.78 7911.42,5214.57 7905.51,5220.47 7901.66,5220.47 7881.89,5240.24 7881.89,5248.03 7858.27,5271.65 7787.4,5271.65 7771.65,5255.91 7771.65,5074.8 7729,5032.15 7729,4802.5 8141.73,4389.76 9468.5,4389.76 9503.94,4354.33 v2(9503.94,4275.59)
  Bottom Layer w5: v2(9503.94,4275.59) 9503.94,4296.83 9506.36,4299.26 R315.2@9506.36,4314.95
NetR318_2: R318.2 U52.15 | length 226.9
  Top Layer w7.87: v1(7842.52,5248.03) 7842.52,5181.1 7852.36,5171.26 7865.35,5171.26 U52.15@7869.09,5171.26
  Bottom Layer w7.87: R318.2@7767.9,5317.39 7767.9,5273.13 7793,5248.03 v1(7842.52,5248.03)
NetR319_2: R319.2 U52.16 | length 287.1
  Top Layer w5: v1(7799.21,5212.6) 7799.21,5187.92 7835.56,5151.57 7865.35,5151.57 U52.16@7869.09,5151.57
  Bottom Layer w5: R319.2@7708.78,5317.39 7708.78,5242.82 7739,5212.6 v1(7799.21,5212.6)
NetTP2_1: TP2.1 U2.1 Y1.2 | length 832.9
  Bottom Layer w7.87: TP2.1@9003.27,5571.82 9038,5537.09 9038,5184.2 9195.63,5026.57 9236.31,5026.57 9347.54,5026.57 9358.29,5037.32 U2.1@9358.29,5078.18
NetU2_2: U2.2 Y1.1 | length 249.8
  Bottom Layer w7.87: Y1.1@9257.91,4932.87 9257.91,5012.21 9259.4,5013.7 9352.87,5013.7 9377.97,5038.8 U2.2@9377.97,5078.18
OUTA1: U31.2 U48.1 | length 282.4
  Bottom Layer w5: U31.2@1070.96,3503.94 1070.97,3570.97
  Bottom Layer w7.87: 1070.97,3570.97 1070.97,3587.97 1080.36,3597.36 1213.87,3597.36 1217.5,3593.74 U48.1@1217.5,3547.24
OUTA2: U34.2 U48.2 | length 472.5
  Bottom Layer w5: U34.2@923.33,3503.94 923.33,3573.9
  Bottom Layer w7.87: 923.33,3573.9 923.33,3588.68 944.88,3610.24 1236.76,3610.24 1242.5,3604.5 U48.2@1242.5,3547.24
OUTA3: U37.2 U48.3 | length 672.1
  Bottom Layer w5: U37.2@775.69,3503.94 775.69,3573.9
  Bottom Layer w7.87: 775.69,3573.9 775.69,3602.46 799.21,3625.98 1256.02,3625.98 1267.5,3614.5 U48.3@1267.5,3547.24
OUTA4: U40.2 U48.4 | length 871.8
  Bottom Layer w5: U40.2@628.05,3503.94 628.05,3573.9
  Bottom Layer w7.87: 628.05,3573.9 628.05,3608.37 661.42,3641.73 1283.27,3641.73 1292.5,3632.5 U48.4@1292.5,3547.24
OUTA5: U43.2 U48.5 | length 1356.8
  Bottom Layer w5: U43.2@186.11,3502.9 186.11,3577.59
  Bottom Layer w7.87: 186.11,3577.59 186.11,3598.11 206.11,3618.11 602.36,3618.11 641.73,3657.48 1309.52,3657.48 1317.5,3649.5 U48.5@1317.5,3547.24
OUTB1: U29.2 U48.6 | length 2548.5
  Bottom Layer w5: U29.2@2970.57,4409.45 2970.57,4494
  Bottom Layer w7.87: U48.6@1342.5,3547.24 1342.5,3628.2 1395.72,3681.42 1885.32,3681.42 1893.7,3689.8 1893.7,3944.88 2011.81,4062.99 2149.61,4062.99 2224.41,4137.8 2224.41,4444.88 2354.33,4574.8 2889.76,4574.8 2970.57,4494
OUTB2: U32.2 U48.7 | length 2368.6
  Bottom Layer w5: 2759.84,4559.06 2822.93,4495.96 U32.2@2822.93,4409.45
  Bottom Layer w7.87: U48.7@1367.5,3547.24 1367.5,3630.2 1405.84,3668.54 1901.33,3668.54 1909.45,3676.67 1909.45,3937.01 2019.69,4047.24 2157.48,4047.24 2244.09,4133.86 2244.09,4441.74 2361.41,4559.06 2759.84,4559.06
OUTB3: U35.2 U48.8 | length 2183.9
  Bottom Layer w5: U35.2@2675.3,4409.45 2675.3,4494
  Bottom Layer w7.87: U48.8@1392.5,3547.24 1392.5,3632.2 1415.97,3655.67 1906.66,3655.67 1925.2,3674.21 1925.2,3929.13 2027.56,4031.5 2169.29,4031.5 2263.78,4125.98 2263.78,4440.94 2366.14,4543.31 2625.98,4543.31 2675.3,4494
OUTB4: U38.2 U48.9 | length 1916.1
  Bottom Layer w5: U38.2@2380.02,4409.45 2380.02,4482.18
  Bottom Layer w7.87: U48.9@1417.5,3547.24 1417.5,3488.5 1421.75,3484.25 1452.64,3484.25 1468.39,3500 1468.39,3615.39 1482.92,3629.92 1917.32,3629.92 1956.69,3669.29 1956.69,3913.39 2043.31,4000 2188.98,4000 2303.15,4114.17 2303.15,4440.94 2350.39,4488.19 2374.02,4488.19 2380.02,4482.18
OUTB5: U41.2 U48.10 | length 1959.2
  Bottom Layer w5: U41.2@2527.66,4409.45 2527.66,4492.03
  Bottom Layer w7.87: U48.10@1442.5,3547.24 1442.5,3617.2 1468.1,3642.8 1911.99,3642.8 1940.94,3671.75 1940.94,3921.26 2035.43,4015.75 2177.17,4015.75 2283.46,4122.05 2283.46,4440.94 2366.14,4523.62 2496.06,4523.62 2527.66,4492.03
OUTC1: U30.2 U49.4 | length 1018.1
  Bottom Layer w5: U30.2@3265.85,4409.45 3265.85,4498.13
  Bottom Layer w7.87: 3265.85,4498.13 3299.21,4531.5 3935.3,4531.5 3970.13,4496.67 3970.13,4380.45 3993,4357.58 4039.37,4357.58 U49.4@4041.34,4357.58
OUTC2: U33.2 U49.2 | length 718.5
  Bottom Layer w5: U33.2@3561.12,4409.45 3561.12,4486.32
  Bottom Layer w7.87: 3561.12,4486.32 3574.8,4500 3930.38,4500 3944.38,4486 3944.38,4356.2 3993,4307.58 4039.37,4307.58 U49.2@4041.34,4307.58
OUTC3: U36.2 U49.3 | length 862
  Bottom Layer w5: U36.2@3413.48,4409.45 3413.48,4480.41
  Bottom Layer w7.87: 3413.48,4480.41 3448.82,4515.75 3932.84,4515.75 3957.25,4491.33 3957.25,4367.33 3992,4332.58 4039.37,4332.58 U49.3@4041.34,4332.58
OUTC4: U39.2 U49.1 | length 559.2
  Bottom Layer w5: U39.2@3708.76,4409.45 3708.76,4476.48
  Bottom Layer w7.87: 3708.76,4476.48 3716.54,4484.25 3921.13,4484.25 3931.5,4473.87 3931.5,4349.5 3998.42,4282.58 4039.37,4282.58 U49.1@4041.34,4282.58
OUTC5: U42.2 U49.5 | length 1165.6
  Bottom Layer w5: U42.2@3118.21,4409.45 3118.21,4504.03
  Bottom Layer w7.87: 3118.21,4504.04 3161.42,4547.24 3937.75,4547.24 3983,4502 3983,4396.58 3997,4382.58 4039.37,4382.58 U49.5@4041.34,4382.58
OUTDB1: U44.2 U48.12 | length 8328.7
  Bottom Layer w7.87: U48.12@1417.5,3342.24 1417.5,3393.5 1422,3398 1452,3398 1464,3386 1464,3206 1449.33,3191.33 1410.33,3191.33 1404,3185 1404,3121.36 1423,3102.36 1790.84,3102.36 2519.93,2373.27 4272.38,2373.27 4859.19,2960.08 5389.87,2960.08 5408,2978.21 5408,3896 5437.2,3925.2 7767.72,3925.2 7783.56,3941.04 U44.2@7783.56,3976.38
OUTDB2: U46.2 U48.11 | length 8445.2
  Bottom Layer w7.87: U48.11@1442.5,3342.24 1442.5,3211.5 1435.21,3204.21 1405,3204.21 1391.13,3190.33 1391.13,3114.55 1423,3082.68 1792.32,3082.68 2514.6,2360.39 4277.72,2360.39 4864.53,2947.2 5395.2,2947.2 5420.87,2972.87 5420.87,3890.67 5439.66,3909.45 7807.09,3909.45 7866.14,3968.5 7905.51,3968.5 7948.82,3925.2 7980.32,3925.2 7990.26,3935.14 U46.2@7990.26,3976.38
OUTUHA: U45.2 U49.6 | length 4714.1
  MidLayer2 w7.87: v1(4507.87,2771.65) 4507.87,2700.79 4909.45,2299.21 v1(4909.45,2023.62)
  MidLayer3 w7.87: v1@5057,1122 5111.87,1067.13 5203.63,1067.13 v1(5221.76,1049)
  Bottom Layer w5: U49.6@4039.37,4408.46 4085.63,4408.46 4090.55,4403.54 4090.55,4267.72 4074.8,4251.97 3976.38,4251.97 3905.51,4181.1 3905.51,3812 3947.51,3770 4305,3770 4424.28,3650.72 4424.28,2898.55 4507.87,2814.96 v1(4507.87,2771.65)
  Bottom Layer w7.87: v1(4909.45,2023.62) 5015.75,1917.32 5015.75,1163.25 v1@5057,1122 ; v1@5222.65,1049 5252.57,1019.09 5427.87,1019.09 5456.78,1048 5456.78,1109.64 5446.84,1119.58 U45.2@5417.41,1119.58
  other v1: 5056.1,1122
OUTUHB: U47.2 U49.7 | length 6185.5
  MidLayer2 w7.87: v1(4539.37,2771.65) 4539.37,2708.66 4937.01,2311.02 4937.01,2015.75 v1(4909.45,1988.19)
  MidLayer3 w7.87: v1@5023,1109 5092,1040 v1(5191.39,1040)
  Bottom Layer w5: U49.7@4039.37,4433.46 4086.22,4433.46 4102.36,4417.32 4102.36,4263.78 4078.74,4240.16 3980.31,4240.16 3917.32,4177.17 3917.32,3818 3955.32,3780 4358,3780 4434.28,3703.72 4434.28,2908.24 4539.37,2803.15 v1(4539.37,2771.65)
  Bottom Layer w7.87: v1(4909.45,1988.19) 4996.06,1901.57 4996.06,1134.94 5022,1109 v1@5023,1109 ; v1@5192.28,1040 5238.28,994 5440,994 5477,1031 5477,1197 5532,1252 6061,1252 6279.08,1033.92 6493.1,1033.92 6524.18,1065 6524.18,1108.72 6510.3,1122.6 U47.2@6473,1122.6
  other v1: 5022.1,1109
PBCTRLA.1W.ID: EXTHDR1.61 R142.1 U5.N1 | length 9653.1
  Top Layer w5: v5(6240.16,3393.7) 6303.15,3393.7 6326.77,3370.08 6326.77,3287.4 6468.72,3145.45 8224.68,3145.45 8718.68,3639.45 9100.11,3639.45 9128.77,3610.79 9229.79,3610.79 9376.01,3464.57 U5.N1@9496.06,3464.57
  Top Layer w7.87: v1(1047.24,3007.87) EXTHDR1.61@1047.24,3086.61
  MidLayer1 w5: v1(1047.24,3007.87) 1047.24,2921.26 1059.05,2909.45 2505.68,2909.45 2651.35,3055.12 2787.4,3055.12 2799.21,3043.31 2830.71,3043.31 2972.44,2901.58 3634.58,2901.58 3673.95,2940.95 4598.43,2940.95 4610.24,2952.76 4834.65,2952.76 4940.95,3059.06 4940.95,3295.28 5047.24,3401.58 6192.91,3401.58 6200.79,3393.7 v5(6240.16,3393.7)
  Bottom Layer w10: R142.1@949.86,2958.45 1023.68,2958.45 1047.24,2982.02 v1(1047.24,3007.87)
PBCTRLA.1W.PIO1: EXTHDR1.69 U5.C10 | length 10365.3
  Top Layer w7.87: v1(9830.71,3877.95) U5.C10@9850.39,3858.27
  Top Layer w10: EXTHDR1.69@921.26,3086.61 921.26,3173.23 1415.52,3667.49 1596.63,3667.49 1901.57,3972.44 1901.57,4397.64 1985.94,4482 6712.55,4482 6959,4728.45 7683.68,4728.45 v1@7838.68,4573.45
  MidLayer1 w5: v1(7838.7,4573.46) 8093.71,4318.45 9193.68,4318.45 9300.14,4212 9655.99,4212 9815.68,4052.31 9815.68,3987.45 9833.68,3969.45 9833.68,3944.4 9830.71,3941.43 v1(9830.71,3877.95)
PBCTRLA.1W.PIO2: EXTHDR1.71 U5.D10 | length 10495.3
  Top Layer w7.87: v1(9830.71,3838.58) U5.D10@9850.39,3818.9
  Top Layer w10: EXTHDR1.71@889.76,3086.61 889.76,3173.23 1405.41,3688.88 1596.8,3688.88 1886.57,3978.65 1886.57,4422.01 1966.77,4502.2 6701.75,4502.2 6948,4748.45 7708.68,4748.45 v1@7883.68,4573.45
  MidLayer1 w5: v1@7883.68,4573.45 8128.68,4328.45 9200.68,4328.45 9307.13,4222 9660.14,4222 9862.2,4019.93 9862.2,3976.38 9850.39,3964.57 9850.39,3858.27 v1(9830.71,3838.58) ; 9862.13,4000 9862.2,4000
  other v1: 7883.7,4573.46
PBCTRLA.CLK.CLK0: EXTHDR1.51 U5.R5 | length 9196.9
  Top Layer w5: EXTHDR1.51@1204.72,3086.61 1204.72,3007.87 1228.35,2984.25 1307.09,2984.25 v1(1330.71,3007.87)
  Top Layer w7.87: v1(9633.86,3366.14) U5.R5@9653.54,3385.83
  MidLayer2 w5: v1(1330.71,3007.87) 1330.71,2984.25 1342.52,2972.44 2751.97,2972.44 2791.34,2933.07 2897.64,2933.07 2913.39,2917.32 4500,2917.32 4566.93,2984.25 5157.48,2984.25 5338.58,3165.35 5338.58,3228.35 5507.87,3397.64 6023.62,3397.64 6358.27,3062.99 8364.84,3062.99 8616.81,3314.96 9045.99,3314.96 9152.95,3208 9294.23,3208 9344.57,3258.35 9358.38,3258.35 9434.68,3334.65 ; 9433.07,3334.65 9492.13,3334.65 9503.94,3346.46 9614.17,3346.46 v1(9633.86,3366.14)
PBCTRLA.CLK.CLK1: EXTHDR1.45 U5.T5 | length 9083
  Top Layer w7.87: v1(1299.21,3007.87) EXTHDR1.45@1299.21,3086.61 ; v1(9633.86,3326.77) U5.T5@9653.54,3346.46
  MidLayer2 w5: v1(1299.21,3007.87) 1299.21,2984.25 1322.83,2960.63 2744.09,2960.63 2783.46,2921.26 2893.7,2921.26 2909.45,2905.51 4503.94,2905.51 4570.87,2972.44 5165.35,2972.44 5350.39,3157.48 5350.39,3220.47 5515.75,3385.83 6019.69,3385.83 6354.33,3051.18 8369.73,3051.18 8621.7,3303.15 9043.66,3303.15 9148.81,3198 9298.37,3198 9348.72,3248.35 9362.52,3248.35 9433.07,3318.9 9492.13,3318.9 9503.94,3307.09 9614.17,3307.09 v1(9633.86,3326.77)
PBCTRLA.CLK.CLK2: EXTHDR1.47 U5.U5 | length 9096.7
  Top Layer w7.87: v1(1267.72,3007.87) EXTHDR1.47@1267.72,3086.61 ; v1(9633.86,3287.4) U5.U5@9653.54,3307.09
  MidLayer2 w5: v1(1267.72,3007.87) 1267.72,2984.25 1303.15,2948.82 2219.31,2948.82 2258.68,2909.45 2889.76,2909.45 2905.51,2893.7 4507.87,2893.7 4574.8,2960.63 5173.23,2960.63 5362.2,3149.61 5362.2,3212.6 5523.62,3374.02 6015.75,3374.02 6350.39,3039.37 8374.62,3039.37 8626.59,3291.34 9041.33,3291.34 9144.67,3188 9302.51,3188 9352.86,3238.35 9482.44,3238.35 9511.81,3267.72 9614.17,3267.72 v1(9633.86,3287.4)
PBCTRLA.CLK.EN: EXTHDR1.49 U5.V5 | length 9122.4
  Top Layer w7.87: v1(1236.22,3007.87) EXTHDR1.49@1236.22,3086.61 ; v1(9633.86,3248.03) U5.V5@9653.54,3267.72
  MidLayer2 w5: v1(1236.22,3007.87) 1236.22,2980.31 1279.53,2937.01 2209.13,2937.01 2248.5,2897.64 2885.83,2897.64 2901.57,2881.89 4511.81,2881.89 4578.74,2948.82 5181.1,2948.82 5336.37,3104.08 5374.02,3141.73 5374.02,3204.73 5531.5,3362.21 6011.81,3362.21 6346.46,3027.56 8379.52,3027.56 8631.48,3279.53 9039,3279.53 9140.53,3178 9306.65,3178 9357,3228.35 9409.45,3228.35 9433.07,3228.35 9614.17,3228.35 v1(9633.86,3248.03)
PBCTRLA.JTAG.DETECT: R206.1 R207.1 U5.N20 | length 10667.9
  Top Layer w7.87: U5.N20@10244.09,3464.57 v5(10266.14,3485.04)
  MidLayer3 w5: v2(1535.43,3389.76) 1535.43,3454.36 1477.61,3512.18 1477.61,3623.28 2078.74,4224.41 4673.23,4224.41 4748.03,4149.61 9165.51,4149.61 9290.7,4274.8 9361.2,4274.8 9446.85,4360.45 10222.55,4360.45 10407,4176 10407,3943.39 10452.76,3897.64 10452.76,3523.62 10433.07,3503.94 10283.47,3503.94 v5(10266.14,3485.04)
  Bottom Layer w11.81: R207.1@1535.43,3322.36 R206.1@1535.43,3455.2
PBCTRLA.JTAG.HARD.TCK: R193.1 R197.1 U5.G20 | length 10041
  Top Layer w7.87: U5.G20@10244.09,3700.79 v1(10263.78,3720.47)
  MidLayer3 w5: v2(2007.87,3387.8) 1898,3497.67 1844.85,3497.67 1807.09,3535.43 1807.09,3854.33 2110.35,4157.6 4645.55,4157.6 4720.36,4082.79 9185.16,4082.79 9317.16,4214.8 9534.94,4214.8 9607.6,4287.45 10210.69,4287.45 10313,4185.15 10313,3940 10272.57,3899.57 10254.7,3899.57 10244.1,3888.96 10244.09,3740.16 v1(10263.78,3720.47)
  Bottom Layer w11.81: R197.1@2007.87,3322.36 R193.1@2007.87,3453.23
PBCTRLA.JTAG.HARD.TDI: R190.1 R194.1 U5.G19 | length 10062
  Top Layer w7.87: U5.G19@10204.72,3700.79 v1(10224.41,3720.47)
  MidLayer3 w5: v2(2086.61,3387.8) 1994.77,3479.64 1933.75,3479.64 1818.9,3594.49 1818.9,3850.39 2114.97,4146.46 4640.94,4146.46 4715.74,4071.66 9189.77,4071.66 9322.91,4204.8 9539.08,4204.8 9609.74,4275.45 10208.55,4275.45 10303,4181 10303,3944.14 10268.43,3909.57 10228.47,3909.57 10204.72,3885.83 10204.72,3740.16 v1(10224.41,3720.47)
  Bottom Layer w11.81: R194.1@2086.61,3322.36 R190.1@2086.61,3453.23
PBCTRLA.JTAG.HARD.TDO: R191.1 R195.1 U5.G18 | length 10078.6
  Top Layer w7.87: U5.G18@10165.35,3700.79 v1(10185.04,3721.26)
  MidLayer3 w5: v2(2165.35,3387.8) 2144.08,3409.07 2086.99,3409.07 1828.9,3667.17 1828.9,3844.65 2119.58,4135.33 4636.33,4135.33 4711.13,4060.52 9194.38,4060.52 9286.05,4152.19 9328.66,4194.8 9543.23,4194.8 9610.88,4262.45 10207.41,4262.45 10293,4176.86 10293,3948.28 10264.28,3919.57 10199.1,3919.57 10165.35,3885.83 10165.35,3740.16 v1(10185.04,3721.26)
  Bottom Layer w11.81: R195.1@2165.35,3322.36 R191.1@2165.35,3453.23
PBCTRLA.JTAG.HARD.TMS: R192.1 R196.1 U5.H20 | length 10035.4
  Top Layer w7.87: U5.H20@10244.09,3661.42 v1(10263.78,3681.1)
  MidLayer3 w5: v2(1929.13,3387.8) 1795.28,3521.65 1795.28,3858.27 2105.74,4168.73 4650.17,4168.73 4724.97,4093.93 9180.54,4093.93 9272.21,4185.6 9311.41,4224.8 9530.8,4224.8 9605.45,4299.45 10212.84,4299.45 10323,4189.29 10323,3925.53 10283.47,3886 10283.47,3700.79 v1(10263.78,3681.1)
  Bottom Layer w11.81: R196.1@1929.13,3322.36 R192.1@1929.13,3453.23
